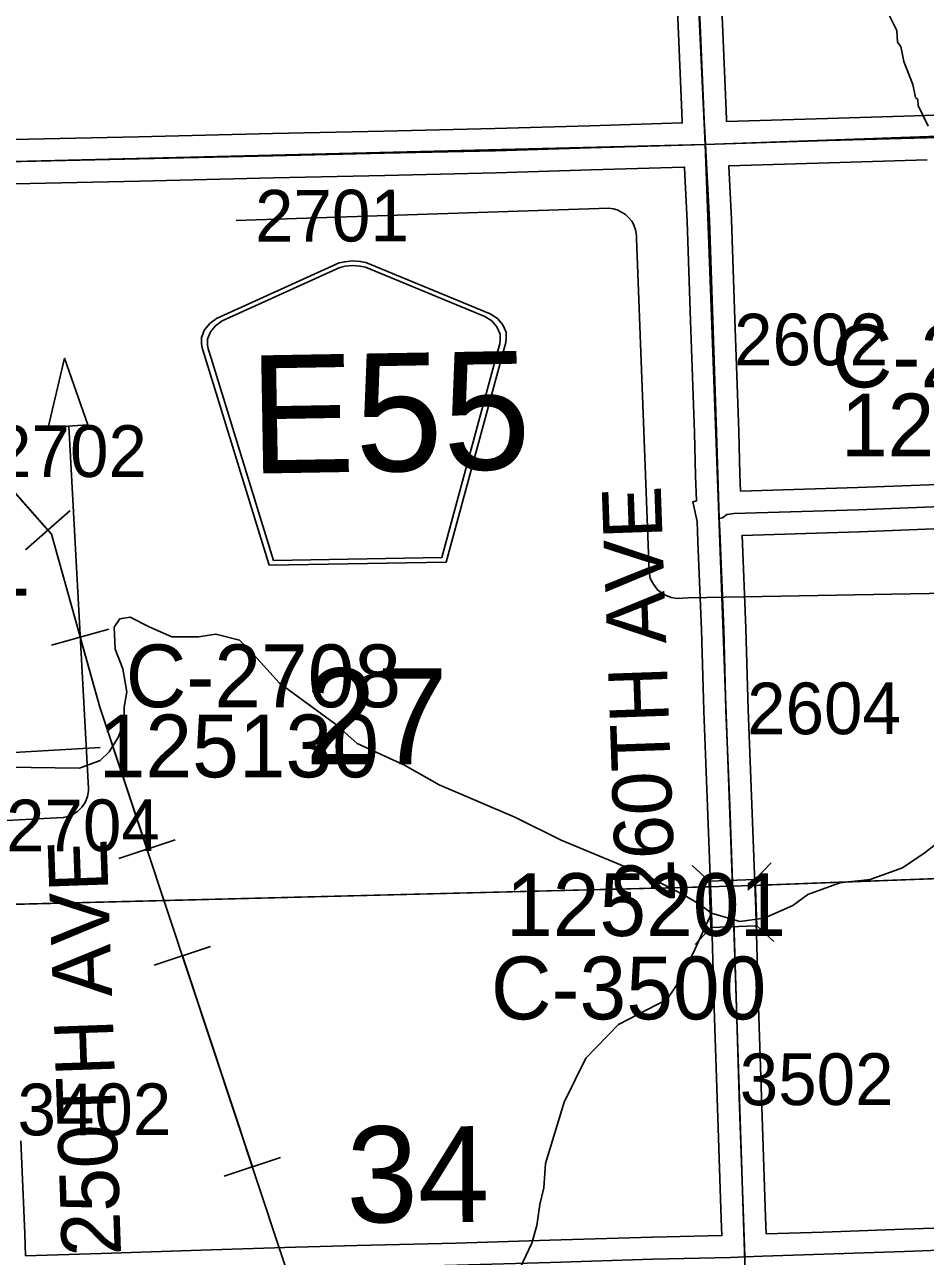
# Model space of a CAD drawing. Extents: x 128.7 to 185.5, y -21.4 to 12.6.
# Drawn here: x 149.009 to 150.229, y -0.713 to 0.955 of the extents above; entities that cross this region are included whole.
import ezdxf

# ---------------------------------------------------------------- set-up
doc = ezdxf.new("R2010")
doc.units = 0
for name, color, linetype in [('tdCoDirctArrow', 7, 'Continuous'), ('tdCoHydroRiver', 7, 'Continuous'), ('tdCoPipe', 7, 'Continuous'), ('tdCoSecRdNmbr', 7, 'Continuous'), ('tdCoSecRdTxt', 7, 'Continuous'), ('tdCoSecRteBand', 7, 'Continuous'), ('tdCoSecRteCL', 7, 'Continuous'), ('tdCoSectLine', 7, 'Continuous'), ('tdCoSectLinePart', 7, 'Continuous'), ('tdCoSectNmbr', 7, 'Continuous'), ('tdCoShieldCoRte', 7, 'Continuous'), ('tdCoStrucSec', 7, 'Continuous'), ('tdCoStrucSecCoName', 7, 'Continuous'), ('tdCoStrucSecFHWANum', 7, 'Continuous'), ('tdCoSurfGravel', 7, 'Continuous')]:
    doc.layers.add(name, color=color, linetype=linetype)

msp = doc.modelspace()

# ---------------------------------------------------------------- linework, layer by layer
at = {"layer": 'tdCoDirctArrow'}
for points in [[(149.2954, 0.6902), (149.7999, 0.7069), (149.8064, 0.7061), (149.8115, 0.7048), (149.8165, 0.7021), (149.8227, 0.6984), (149.8269, 0.6942), (149.8315, 0.6887), (149.8338, 0.6839), (149.8361, 0.6775), (149.8376, 0.6699), (149.8376, 0.6657), (149.8546, 0.2151), (149.8562, 0.2055), (149.8604, 0.1974), (149.8658, 0.1898), (149.8746, 0.1836), (149.8845, 0.1794), (149.8926, 0.1783), (149.9075, 0.179), (150.3841, 0.1878)], [(148.7293, -0.1362), (149.0616, -0.1186), (149.0683, -0.117), (149.074, -0.1146), (149.0809, -0.1101), (149.0866, -0.1046), (149.0911, -0.0979), (149.0943, -0.09), (149.0957, -0.0822), (149.0957, -0.0791), (149.0692, 0.4114)]]:
    msp.add_lwpolyline(points, dxfattribs=at)
msp.add_lwpolyline([(149.0411, 0.41), (149.0634, 0.5037), (149.0949, 0.4134)], close=True, dxfattribs=at)
at = {"layer": 'tdCoHydroRiver'}
for points in [[(150.2325, 0.8181), (150.2189, 0.846), (150.2186, 0.8539), (150.2154, 0.8569), (150.2116, 0.8742), (150.1995, 0.9053), (150.1956, 0.9257), (150.1907, 0.9318), (150.1902, 0.9476), (150.1749, 0.9771)], [(148.9193, -0.0492), (149.0835, -0.0515), (149.1115, -0.041), (149.1237, -0.0296), (149.1357, -0.0102), (149.1415, 0.0042), (149.1446, 0.0074), (149.1438, 0.0311), (149.1478, 0.0517), (149.142, 0.0831), (149.1316, 0.1096), (149.1306, 0.1395), (149.1381, 0.1508), (149.1522, 0.1529), (149.1779, 0.1396), (149.2083, 0.1264), (149.2447, 0.1261), (149.2682, 0.13), (149.3, 0.1217), (149.3115, 0.111), (149.3541, 0.0636), (149.4302, 0.0078), (149.4595, -0.018), (149.5236, -0.0474), (149.5703, -0.0742), (149.6728, -0.118), (149.7354, -0.149), (149.8507, -0.1971), (149.9021, -0.2238), (149.923, -0.2357), (149.9392, -0.2478), (149.9775, -0.2591), (150.0105, -0.2548), (150.0494, -0.2377), (150.0694, -0.2228), (150.113, -0.2071), (150.1539, -0.2025), (150.1975, -0.1868), (150.2268, -0.1669), (150.2791, -0.1272)], [(149.9392, -0.2478), (149.9143, -0.3023), (149.8906, -0.3473), (149.8786, -0.365), (149.8134, -0.3988), (149.7692, -0.4446), (149.7397, -0.504), (149.7142, -0.5869), (149.7121, -0.6201), (149.7066, -0.6424), (149.7028, -0.6709), (149.6958, -0.6948), (149.6722, -0.7446)]]:
    msp.add_lwpolyline(points, dxfattribs=at)
at = {"layer": 'tdCoPipe'}
for p, q in [((149.0105, 0.2442), (149.071, 0.2975)), ((149.0458, 0.115), (149.1233, 0.1367)), ((149.1367, -0.174), (149.2132, -0.1486)), ((149.1845, -0.3184), (149.2609, -0.293)), ((149.2792, -0.6042), (149.3558, -0.5788))]:
    msp.add_line(p, q, dxfattribs=at)
for points in [[(148.6284, 1.2813), (148.7667, 0.7397), (148.8239, 0.5169), (149.0454, 0.2655), (149.1111, 0.0311), (149.7815, -1.9917), (149.8869, -2.2086), (150.0884, -2.36), (150.353, -3.1907), (150.6682, -4.2821), (150.7734, -4.4455), (150.8791, -4.6209), (150.9399, -4.7309), (150.9845, -4.7883), (151.1763, -4.8453), (151.8715, -6.5252), (151.9475, -6.6623), (151.9951, -7.1544), (151.9928, -7.2474), (152.3334, -7.551)], [(148.8416, 0.4967), (149.0408, 0.2708)], [(149.0846, 0.1259), (149.1111, 0.0311), (149.1749, -0.1613)], [(149.2228, -0.3057), (149.3175, -0.5915)]]:
    msp.add_lwpolyline(points, dxfattribs=at)
at = {"layer": 'tdCoSecRteBand'}
for points in [[(149.9489, 1.0693), (149.9543, 0.9456), (149.9543, 0.9455), (149.9543, 0.9455), (149.9592, 0.8277), (149.9594, 0.8241)], [(148.9504, 0.7988), (149.1636, 0.8036), (149.3446, 0.8078), (149.3446, 0.8078), (149.3446, 0.8078), (149.4956, 0.8113), (149.6459, 0.8147), (149.7745, 0.8186), (149.7745, 0.8186), (149.7745, 0.8186), (149.8994, 0.8223), (149.8993, 0.8248), (149.8993, 0.825), (149.8993, 0.8251), (149.8944, 0.943), (149.8889, 1.0667)], [(149.9594, 0.8241), (150.0961, 0.8283), (150.0961, 0.8283), (150.0961, 0.8283), (150.229, 0.8322), (150.3129, 0.8359), (150.3131, 0.8359), (150.3133, 0.8359), (150.4821, 0.8411), (150.6396, 0.8472), (150.6396, 0.8472), (150.6396, 0.8472), (150.8057, 0.8537), (150.8712, 0.8566), (150.8647, 0.977)], [(150.231, 0.7722), (150.0979, 0.7683), (149.9625, 0.7641), (149.9661, 0.6915), (149.9662, 0.6913), (149.9662, 0.691), (149.9708, 0.5564), (149.9708, 0.5564), (149.9708, 0.5564), (149.976, 0.4045), (149.976, 0.4043), (149.976, 0.4042), (149.9775, 0.3462), (149.9783, 0.3236)], [(149.0104, -0.7121), (149.1129, -0.7088), (149.1129, -0.7088), (149.1129, -0.7088), (149.2618, -0.7041), (149.376, -0.7005), (149.3761, -0.7004), (149.3762, -0.7004), (149.4588, -0.6982), (149.4588, -0.6982), (149.4588, -0.6982), (149.5934, -0.6948), (149.7201, -0.6911), (149.8589, -0.6866), (149.859, -0.6866), (149.8592, -0.6866), (149.9531, -0.6846), (149.9523, -0.662), (149.9523, -0.662), (149.9523, -0.662), (149.9471, -0.5118), (149.9471, -0.5117), (149.9471, -0.5117), (149.9429, -0.3765), (149.9429, -0.3765), (149.9429, -0.3765), (149.939, -0.2454), (149.9338, -0.1033), (149.9286, 0.0257), (149.9286, 0.0259), (149.9286, 0.0261), (149.9257, 0.1358), (149.9208, 0.2553), (149.9207, 0.2553), (149.9203, 0.2689), (149.9203, 0.2689), (149.9203, 0.2689), (149.9198, 0.2826), (149.9139, 0.3092), (149.9188, 0.3103), (149.9175, 0.3441), (149.9175, 0.3443), (149.9175, 0.3445), (149.9161, 0.4025), (149.9109, 0.5543), (149.9062, 0.6887), (149.9025, 0.7617), (149.9025, 0.7624), (149.9018, 0.7624), (149.7763, 0.7587), (149.6476, 0.7547), (149.6475, 0.7547), (149.6474, 0.7547), (149.4969, 0.7513), (149.346, 0.7478), (149.165, 0.7436), (149.165, 0.7436), (149.165, 0.7436), (148.9527, 0.7389)], [(149.9783, 0.3236), (150.1373, 0.3285), (150.294, 0.3346)], [(150.2962, 0.2747), (150.1395, 0.2685), (150.1394, 0.2685), (150.1392, 0.2685), (149.9805, 0.2636), (149.9856, 0.1381), (149.9856, 0.1379), (149.9857, 0.1377), (149.9886, 0.0279), (149.9938, -0.1009), (149.9938, -0.101), (149.9938, -0.101), (149.999, -0.2433), (149.999, -0.2434), (149.999, -0.2435), (150.0029, -0.3747), (150.0071, -0.5098), (150.0123, -0.6599), (150.0131, -0.6823)], [(149.0042, -0.5563), (149.0093, -0.682), (149.0093, -0.6822), (149.0094, -0.6823), (149.0104, -0.7121)], [(150.0131, -0.6823), (150.0902, -0.68), (150.1996, -0.676), (150.1996, -0.676), (150.1996, -0.676), (150.3065, -0.6723)]]:
    msp.add_lwpolyline(points, dxfattribs=at)
at = {"layer": 'tdCoSecRteCL'}
for points in [[(149.931, 0.7932), (149.9293, 0.8264), (149.9243, 0.9442), (149.9189, 1.068), (149.913, 1.1975), (149.9071, 1.3294), (149.9012, 1.4722), (149.8935, 1.6017), (149.8874, 1.7243), (149.8835, 1.7983)], [(149.931, 0.7932), (149.9438, 0.7936), (150.097, 0.7983), (150.2302, 0.8022), (150.3142, 0.8059), (150.4832, 0.8111), (150.6408, 0.8173), (150.807, 0.8237), (150.9029, 0.828)], [(148.9216, 0.7682), (148.9446, 0.7687), (149.1643, 0.7736), (149.3453, 0.7778), (149.4962, 0.7813), (149.6467, 0.7847), (149.7754, 0.7887), (149.931, 0.7932)], [(149.9496, 0.2864), (149.9475, 0.3452), (149.946, 0.4034), (149.9409, 0.5553), (149.9362, 0.69), (149.931, 0.7932)], [(149.9496, 0.2864), (149.9541, 0.2874), (149.9598, 0.2921), (149.9694, 0.2933), (150.1383, 0.2985), (150.2952, 0.3047), (150.456, 0.3096), (150.6007, 0.3155), (150.7127, 0.319), (150.8224, 0.3227), (150.9281, 0.3266)], [(149.9842, -0.7135), (149.9823, -0.6609), (149.9771, -0.5107), (149.9729, -0.3756), (149.969, -0.2444), (149.9638, -0.1021), (149.9586, 0.0269), (149.9557, 0.1368), (149.9502, 0.27), (149.9496, 0.2864)], [(149.9842, -0.7135), (150.0083, -0.7124), (150.0911, -0.71), (150.2006, -0.706), (150.3077, -0.7023), (150.4152, -0.6976), (150.4948, -0.6952), (150.6154, -0.6907), (150.7269, -0.6873), (150.8482, -0.6821), (150.9793, -0.6784)]]:
    msp.add_lwpolyline(points, dxfattribs=at)
at = {"layer": 'tdCoSectLine'}
for points in [[(149.8831, 1.7983), (149.9306, 0.7932)], [(149.9306, 0.7932), (150.9025, 0.828)], [(148.9212, 0.7682), (149.9306, 0.7932)], [(149.9306, 0.7932), (149.9674, -0.2114)], [(149.9674, -0.2114), (150.9536, -0.1746)], [(148.961, -0.2369), (149.9674, -0.2114)], [(149.9674, -0.2114), (150.0007, -1.2153)]]:
    msp.add_lwpolyline(points, dxfattribs=at)
at = {"layer": 'tdCoSectLinePart'}
for points in [[(149.9974, -0.2103), (150.9236, -0.1757)], [(148.9909, -0.2361), (149.937, -0.2122)]]:
    msp.add_lwpolyline(points, dxfattribs=at)
at = {"layer": 'tdCoShieldCoRte'}
for points in [[(149.3405, 0.2233), (149.2537, 0.5047), (149.2495, 0.5178), (149.2487, 0.5237), (149.2486, 0.5315), (149.2526, 0.5419), (149.2598, 0.5505), (149.2692, 0.5574), (149.4352, 0.6326), (149.4427, 0.6344), (149.4531, 0.6355), (149.4635, 0.6347), (149.4711, 0.6332), (149.6396, 0.5638), (149.6493, 0.5573), (149.6567, 0.549), (149.6611, 0.5387), (149.6613, 0.5309), (149.6606, 0.525), (149.657, 0.5118), (149.58, 0.2275)], [(149.3463, 0.2298), (149.2617, 0.5036), (149.2578, 0.5162), (149.257, 0.5218), (149.2569, 0.5293), (149.2608, 0.5393), (149.2676, 0.5475), (149.2767, 0.5541), (149.436, 0.6264), (149.4432, 0.6281), (149.4532, 0.6291), (149.4632, 0.6284), (149.4705, 0.627), (149.6323, 0.5603), (149.6416, 0.5541), (149.6487, 0.546), (149.6529, 0.5362), (149.6531, 0.5287), (149.6525, 0.5231), (149.649, 0.5104), (149.574, 0.2337)]]:
    msp.add_lwpolyline(points, close=True, dxfattribs=at)
at = {"layer": 'tdCoStrucSec'}
for p, q in [((149.9358, -0.2048), (149.9129, -0.1835)), ((149.9984, -0.2025), (150.0197, -0.1796)), ((150.0007, -0.2651), (150.0236, -0.2864)), ((149.9381, -0.2674), (149.9168, -0.2903))]:
    msp.add_line(p, q, dxfattribs=at)
msp.add_lwpolyline([(149.9381, -0.2674), (149.9358, -0.2048), (149.9984, -0.2025), (150.0007, -0.2651)], close=True, dxfattribs=at)
at = {"layer": 'tdCoStrucSecFHWANum'}
msp.add_line((149.1115, -0.0235), (148.9503, -0.0328), dxfattribs=at)
at = {"layer": 'tdCoSurfGravel'}
for points in [[(149.931, 0.7932), (149.9293, 0.8264), (149.9243, 0.9442), (149.9189, 1.068), (149.913, 1.1975), (149.9071, 1.3294), (149.9012, 1.4722), (149.8935, 1.6017), (149.8874, 1.7243), (149.8835, 1.7983), (149.8812, 1.8421), (149.877, 1.9487), (149.8703, 2.0564), (149.8654, 2.1681), (149.8587, 2.305), (149.8533, 2.4204), (149.8481, 2.5447), (149.8425, 2.6715), (149.8361, 2.7945), (149.8339, 2.8522), (149.8334, 2.8927), (149.8319, 2.9067)], [(149.931, 0.7932), (149.9438, 0.7936), (150.097, 0.7983), (150.2302, 0.8022), (150.3142, 0.8059), (150.4832, 0.8111), (150.6408, 0.8173), (150.807, 0.8237), (150.9029, 0.828), (150.9226, 0.8289), (151.0661, 0.8365), (151.1803, 0.8414), (151.3954, 0.8501), (151.5527, 0.856), (151.6637, 0.8609), (151.785, 0.8658), (151.8992, 0.8705), (151.9183, 0.8711)], [(148.9216, 0.7682), (148.9446, 0.7687), (149.1643, 0.7736), (149.3453, 0.7778), (149.4962, 0.7813), (149.6467, 0.7847), (149.7754, 0.7887), (149.931, 0.7932)], [(149.9496, 0.2864), (149.9475, 0.3452), (149.946, 0.4034), (149.9409, 0.5553), (149.9362, 0.69), (149.931, 0.7932)], [(149.9496, 0.2864), (149.9541, 0.2874), (149.9598, 0.2921), (149.9694, 0.2933), (150.1383, 0.2985), (150.2952, 0.3047), (150.456, 0.3096), (150.6007, 0.3155), (150.7127, 0.319), (150.8224, 0.3227), (150.9281, 0.3266), (150.9561, 0.3276), (151.1344, 0.3357), (151.2601, 0.3402), (151.396, 0.3468), (151.54, 0.3523), (151.6703, 0.3572), (151.7903, 0.3636), (151.9398, 0.3694)], [(149.9842, -0.7135), (149.9823, -0.6609), (149.9771, -0.5107), (149.9729, -0.3756), (149.969, -0.2444), (149.9638, -0.1021), (149.9586, 0.0269), (149.9557, 0.1368), (149.9502, 0.27), (149.9496, 0.2864)], [(148.9814, -0.7429), (148.9977, -0.7425), (149.1138, -0.7388), (149.2628, -0.7341), (149.377, -0.7304), (149.4596, -0.7282), (149.5942, -0.7248), (149.721, -0.7211), (149.8598, -0.7166), (149.9649, -0.7144), (149.9842, -0.7135), (150.0083, -0.7124), (150.0911, -0.71), (150.2006, -0.706), (150.3077, -0.7023), (150.4152, -0.6976), (150.4948, -0.6952), (150.6154, -0.6907), (150.7269, -0.6873), (150.8482, -0.6821), (150.9793, -0.6784)]]:
    msp.add_lwpolyline(points, dxfattribs=at)

# ---------------------------------------------------------------- texts
at = {"layer": 'tdCoSecRdNmbr'}
for s, rotation, p in [('2701', 0.1135, (149.3212, 0.6615)), ('2602', 0.114, (149.9698, 0.4938)), ('2702', 0.1132, (148.9666, 0.3425)), ('2604', 0.114, (149.9874, -0.0058)), ('2704', 0.1132, (148.9841, -0.1643)), ('3502', 0.114, (149.9774, -0.5081)), ('3402', 0.1132, (148.9996, -0.5489))]:
    msp.add_text(s, height=0.07, rotation=rotation, dxfattribs=at).set_placement(p)
at = {"layer": 'tdCoSecRdTxt'}
for s, p in [('260TH AVE', (149.8901, -0.233)), ('250TH AVE', (149.1399, -0.7111))]:
    msp.add_text(s, height=0.08, rotation=92, dxfattribs=at).set_placement(p)
at = {"layer": 'tdCoSectNmbr'}
for s, p in [('27', (149.389, -0.0466)), ('34', (149.445, -0.6668))]:
    msp.add_text(s, height=0.13, rotation=0.1135, dxfattribs=at).set_placement(p)
at = {"layer": 'tdCoShieldCoRte'}
msp.add_text('E55', height=0.16, rotation=1, dxfattribs=at).set_placement((149.3147, 0.3472))
at = {"layer": 'tdCoStrucSecCoName'}
for s, p in [('C-2635', (150.1019, 0.4642)), ('C-2708', (149.1461, 0.0309)), ('C-3500', (149.6405, -0.3918))]:
    msp.add_text(s, height=0.085, dxfattribs=at).set_placement(p)
at = {"layer": 'tdCoStrucSecFHWANum'}
for s, p in [('125121', (150.1143, 0.3707)), ('125141', (148.638, 0.1822)), ('125130', (149.1095, -0.064)), ('125201', (149.6609, -0.2789))]:
    msp.add_text(s, height=0.085, dxfattribs=at).set_placement(p)

doc.saveas('drawing.dxf')
